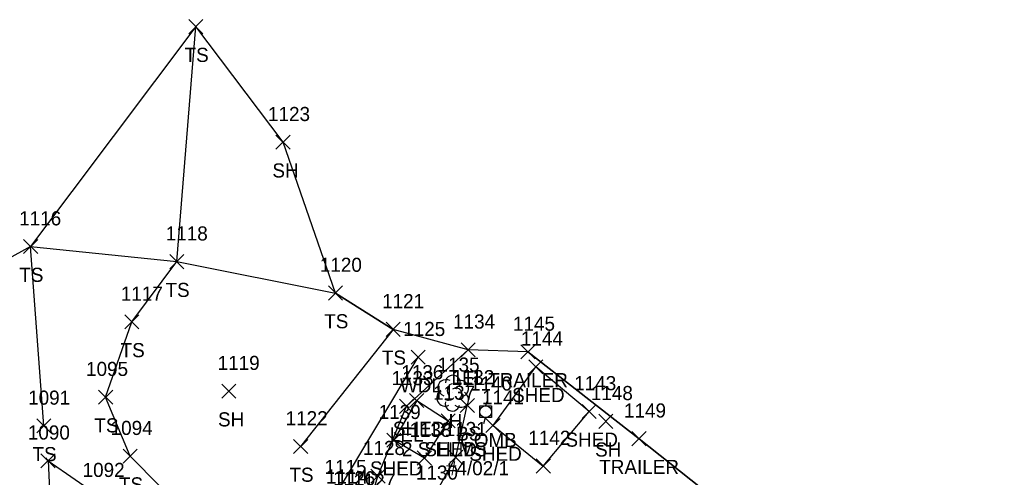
# Model space of a CAD drawing. Extents: x 1638344 to 1639591, y 610835 to 612202.
# Drawn here: x 1638740.9 to 1638879.7, y 611802.5 to 611867.3 of the extents above; entities that cross this region are included whole.
import ezdxf

# ---------------------------------------------------------------- set-up
doc = ezdxf.new("R2010")
doc.units = 0
for name, color, linetype in [('L_A', 7, 'Continuous'), ('L_C', 7, 'Continuous'), ('L_I', 7, 'Continuous'), ('L_TIC', 7, 'Continuous'), ('LARO', 7, 'Continuous'), ('LAWA', 7, 'Continuous'), ('LBC', 7, 'Continuous'), ('LELB', 7, 'Continuous'), ('LSOGP', 7, 'Continuous'), ('LTD', 7, 'Continuous'), ('U_A', 7, 'Continuous'), ('U_C', 7, 'Continuous'), ('U_I', 7, 'Continuous'), ('UP', 7, 'Continuous')]:
    doc.layers.add(name, color=color, linetype=linetype)

msp = doc.modelspace()

# ---------------------------------------------------------------- linework, layer by layer
at = {"layer": 'L_TIC'}
for points in [[(1638764.83, 611865.31), (1638766.83, 611867.31)], [(1638766.83, 611865.31), (1638764.83, 611867.31)], [(1638777.18, 611848.94), (1638779.18, 611850.94)], [(1638779.18, 611848.94), (1638777.18, 611850.94)], [(1638741.44, 611834.16), (1638743.44, 611836.16)], [(1638743.44, 611834.16), (1638741.44, 611836.16)], [(1638762.13, 611832.02), (1638764.13, 611834.02)], [(1638764.13, 611832.02), (1638762.13, 611834.02)], [(1638762.13, 611832.02), (1638764.13, 611834.02)], [(1638764.13, 611832.02), (1638762.13, 611834.02)], [(1638784.6, 611827.58), (1638786.6, 611829.58)], [(1638786.6, 611827.58), (1638784.6, 611829.58)], [(1638755.77, 611823.49), (1638757.77, 611825.49)], [(1638757.77, 611823.49), (1638755.77, 611825.49)], [(1638792.76, 611822.43), (1638794.76, 611824.43)], [(1638794.76, 611822.43), (1638792.76, 611824.43)], [(1638796.32, 611818.49), (1638798.32, 611820.49)], [(1638798.32, 611818.49), (1638796.32, 611820.49)], [(1638803.38, 611819.54), (1638805.38, 611821.54)], [(1638805.38, 611819.54), (1638803.38, 611821.54)], [(1638811.85, 611819.24), (1638813.85, 611821.24)], [(1638813.85, 611819.24), (1638811.85, 611821.24)], [(1638812.98, 611817.13), (1638814.98, 611819.13)], [(1638814.98, 611817.13), (1638812.98, 611819.13)], [(1638812.98, 611817.13), (1638814.98, 611819.13)], [(1638814.98, 611817.13), (1638812.98, 611819.13)], [(1638752.06, 611812.83), (1638754.06, 611814.83)], [(1638754.06, 611812.83), (1638752.06, 611814.83)], [(1638769.49, 611813.68), (1638771.49, 611815.68)], [(1638771.49, 611813.68), (1638769.49, 611815.68)], [(1638794.66, 611811.53), (1638796.66, 611813.53)], [(1638796.66, 611811.53), (1638794.66, 611813.53)], [(1638796.1, 611812.36), (1638798.1, 611814.36)], [(1638798.1, 611812.36), (1638796.1, 611814.36)], [(1638796.1, 611812.36), (1638798.1, 611814.36)], [(1638798.1, 611812.36), (1638796.1, 611814.36)], [(1638803.26, 611811.66), (1638805.26, 611813.66)], [(1638805.26, 611811.66), (1638803.26, 611813.66)], [(1638820.52, 611810.81), (1638822.52, 611812.81)], [(1638822.52, 611810.81), (1638820.52, 611812.81)], [(1638743.3, 611808.76), (1638745.3, 611810.76)], [(1638745.3, 611808.76), (1638743.3, 611810.76)], [(1638800.55, 611809.46), (1638802.55, 611811.46)], [(1638802.55, 611809.46), (1638800.55, 611811.46)], [(1638806.91, 611808.81), (1638808.91, 611810.81)], [(1638808.91, 611808.81), (1638806.91, 611810.81)], [(1638806.91, 611808.81), (1638808.91, 611810.81)], [(1638808.91, 611808.81), (1638806.91, 611810.81)], [(1638822.87, 611809.41), (1638824.87, 611811.41)], [(1638824.87, 611809.41), (1638822.87, 611811.41)], [(1638779.67, 611805.84), (1638781.67, 611807.84)], [(1638781.67, 611805.84), (1638779.67, 611807.84)], [(1638792.86, 611806.73), (1638794.86, 611808.73)], [(1638794.86, 611806.73), (1638792.86, 611808.73)], [(1638792.86, 611806.73), (1638794.86, 611808.73)], [(1638794.86, 611806.73), (1638792.86, 611808.73)], [(1638827.58, 611806.94), (1638829.58, 611808.94)], [(1638829.58, 611806.94), (1638827.58, 611808.94)], [(1638755.54, 611804.47), (1638757.54, 611806.47)], [(1638757.54, 611804.47), (1638755.54, 611806.47)], [(1638743.91, 611803.82), (1638745.91, 611805.82)], [(1638745.91, 611803.82), (1638743.91, 611805.82)], [(1638743.91, 611803.82), (1638745.91, 611805.82)], [(1638745.91, 611803.82), (1638743.91, 611805.82)], [(1638797.19, 611804.2), (1638799.19, 611806.2)], [(1638799.19, 611804.2), (1638797.19, 611806.2)], [(1638801.62, 611804.31), (1638803.62, 611806.31)], [(1638803.62, 611804.31), (1638801.62, 611806.31)], [(1638814.02, 611803.07), (1638816.02, 611805.07)], [(1638816.02, 611803.07), (1638814.02, 611805.07)], [(1638790.62, 611801.63), (1638792.62, 611803.63)], [(1638792.62, 611801.63), (1638790.62, 611803.63)]]:
    msp.add_lwpolyline(points, dxfattribs=at)
at = {"layer": 'LARO'}
msp.add_lwpolyline([(1638790.24, 611797.98), (1638791.62, 611802.63), (1638795.66, 611812.53), (1638804.38, 611820.54)], dxfattribs=at)
at = {"layer": 'LAWA'}
for points in [[(1638744.91, 611804.82), (1638752.57, 611799.52), (1638765.1, 611796.81), (1638772.62, 611792.56), (1638785.61, 611799.94), (1638797.32, 611819.49)], [(1638744.91, 611804.82), (1638745.51, 611792.4)]]:
    msp.add_lwpolyline(points, dxfattribs=at)
at = {"layer": 'LBC'}
for points in [[(1638812.85, 611820.24), (1638828.58, 611807.94), (1638844.61, 611795.24), (1638848.09, 611792.32), (1638864.73, 611779.22), (1638873.51, 611789.89)], [(1638807.91, 611809.81), (1638815.02, 611804.07), (1638821.52, 611811.81), (1638813.98, 611818.13)], [(1638807.91, 611809.81), (1638813.98, 611818.13)], [(1638797.1, 611813.36), (1638801.55, 611810.46), (1638798.19, 611805.2), (1638793.86, 611807.73)], [(1638797.1, 611813.36), (1638793.86, 611807.73)]]:
    msp.add_lwpolyline(points, dxfattribs=at)
at = {"layer": 'LELB'}
for points in [[(1638744.3, 611809.76), (1638742.44, 611835.16), (1638763.13, 611833.02), (1638765.83, 611866.31)], [(1638765.1, 611796.81), (1638756.54, 611805.47), (1638753.06, 611813.83), (1638756.77, 611824.49), (1638763.13, 611833.02), (1638785.6, 611828.58), (1638793.76, 611823.43), (1638780.67, 611806.84)], [(1638790.24, 611797.98), (1638792.84, 611793.99), (1638799.21, 611799.14), (1638802.62, 611805.31), (1638804.26, 611812.66)]]:
    msp.add_lwpolyline(points, dxfattribs=at)
at = {"layer": 'LSOGP'}
msp.add_lwpolyline([(1638882.1, 611783.04), (1638873.51, 611789.89), (1638864.73, 611779.22), (1638848.09, 611792.32), (1638844.61, 611795.24), (1638828.58, 611807.94), (1638812.85, 611820.24), (1638804.38, 611820.54), (1638793.76, 611823.43), (1638785.6, 611828.58), (1638778.18, 611849.94), (1638765.83, 611866.31), (1638742.44, 611835.16), (1638718.34, 611821.86)], dxfattribs=at)
at = {"layer": 'LTD'}
msp.add_line((1638802.18, 611814.44), (1638802.18, 611814.44), dxfattribs=at)
msp.add_line((1638802.18, 611814.44), (1638802.18, 611814.44), dxfattribs=at)
msp.add_arc((1638802.22, 611815.88), 1.05, 335.5272, 180.9563, dxfattribs=at)
for centre, major_axis, ratio, start_param, end_param in [((1638801.38, 611815.11), (1.21, -0.51), 0.895232, 1.570796, 4.712389), ((1638803.22, 611815.03), (-1.14, -0.48), 0.949671, 1.570796, 4.712389), ((1638801.09, 611813.74), (0.58, -1.04), 0.959034, 3.141593, 6.283185), ((1638801.97, 611814.9), (-0.208, -0.792), 0.645439, 3.141593, 6.283185), ((1638802.68, 611814.28), (-0.5, 0.667), 0.989748, 3.141593, 6.283185), ((1638801.72, 611813.69), (-0.625, -0.083), 0.423636, 0, 3.141593), ((1638803.18, 611813.61), (-1.09, 0.79), 0.841452, 1.570796, 4.712389), ((1638802.18, 611812.94), (0.26, 1.06), 0.942809, 1.570796, 4.712389)]:
    msp.add_ellipse(centre, major_axis=major_axis, ratio=ratio, start_param=start_param, end_param=end_param, dxfattribs=at)
at = {"layer": 'UP'}
for p, q in [((1638807.11, 611813.43), (1638806.86, 611812.59)), ((1638806.03, 611810.93), (1638806.03, 611812.59)), ((1638806.03, 611812.59), (1638807.69, 611812.59)), ((1638807.69, 611812.59), (1638807.69, 611810.93)), ((1638807.69, 611810.93), (1638806.03, 611810.93)), ((1638806.61, 611810.09), (1638806.86, 611810.93)), ((1638806.86, 611811.76), (1638806.86, 611811.76))]:
    msp.add_line(p, q, dxfattribs=at)
msp.add_circle((1638806.86, 611811.76), 0.833, dxfattribs=at)

# ---------------------------------------------------------------- texts
at = {"layer": 'L_A'}
for s, p in [('TS', (1638764.24, 611861.31)), ('SH', (1638776.67, 611844.94)), ('TS', (1638740.84, 611830.16)), ('TS', (1638761.54, 611828.02)), ('TS', (1638761.54, 611828.02)), ('TS', (1638784.01, 611823.58)), ('TS', (1638755.18, 611819.49)), ('TS', (1638792.17, 611818.43)), ('LEL', (1638802.02, 611815.54)), ('WDL', (1638794.73, 611814.49)), ('TRAILER', (1638807.21, 611815.24)), ('SHED', (1638810.61, 611813.13)), ('SHED', (1638810.61, 611813.13)), ('TS', (1638751.47, 611808.83)), ('SH', (1638768.97, 611809.68)), ('H', (1638801.61, 611809.44)), ('LEL', (1638793.3, 611807.53)), ('SHED', (1638793.73, 611808.36)), ('SHED', (1638793.73, 611808.36)), ('BS', (1638802.7, 611807.66)), ('SHED', (1638818.16, 611806.81)), ('TS', (1638742.71, 611804.76)), ('SHED', (1638798.19, 611805.46)), ('SHED', (1638804.55, 611804.81)), ('SHED', (1638804.55, 611804.81)), ('SH', (1638822.36, 611805.41)), ('TRAILER', (1638822.94, 611802.94)), ('TS', (1638779.08, 611801.84)), ('SHED', (1638790.49, 611802.73)), ('SHED', (1638790.49, 611802.73)), ('TS', (1638754.95, 611800.47))]:
    msp.add_text(s, height=2, dxfattribs=at).set_placement(p)
at = {"layer": 'L_C'}
msp.add_text('2 S ELMS', height=2, dxfattribs=at).set_placement((1638795.01, 611805.44))
at = {"layer": 'L_I'}
for s, p in [('1123', (1638776.05, 611852.94)), ('1116', (1638740.82, 611838.16)), ('1118', (1638761.57, 611836.02)), ('1118', (1638761.57, 611836.02)), ('1120', (1638783.39, 611831.58)), ('1117', (1638755.21, 611827.49)), ('1121', (1638792.2, 611826.43)), ('1125', (1638795.19, 611822.49)), ('1134', (1638802.25, 611823.54)), ('1145', (1638810.73, 611823.24)), ('1144', (1638811.85, 611821.13)), ('1144', (1638811.85, 611821.13)), ('1095', (1638750.29, 611816.83)), ('1119', (1638768.92, 611817.68)), ('1135', (1638800.05, 611817.44)), ('1133', (1638793.54, 611815.53)), ('1136', (1638794.92, 611816.36)), ('1136', (1638794.92, 611816.36)), ('1132', (1638802.13, 611815.66)), ('1143', (1638819.4, 611814.81)), ('1091', (1638742.09, 611812.76)), ('1137', (1638799.42, 611813.46)), ('1141', (1638806.35, 611812.81)), ('1141', (1638806.35, 611812.81)), ('1148', (1638821.75, 611813.41)), ('1139', (1638791.72, 611810.73)), ('1139', (1638791.72, 611810.73)), ('1149', (1638826.45, 611810.94)), ('1094', (1638753.77, 611808.47)), ('1122', (1638778.54, 611809.84)), ('1090', (1638742.05, 611807.82)), ('1090', (1638742.05, 611807.82)), ('1138', (1638796.07, 611808.2)), ('1131', (1638801.06, 611808.31)), ('1142', (1638812.9, 611807.07)), ('1128', (1638789.49, 611805.63)), ('1115', (1638784.05, 611802.94)), ('1092', (1638749.8, 611802.52)), ('1114', (1638784.25, 611801.58)), ('1130', (1638796.99, 611802.14)), ('1126', (1638785.28, 611801.33)), ('1127', (1638788.11, 611800.98)), ('1127', (1638788.11, 611800.98))]:
    msp.add_text(s, height=2, dxfattribs=at).set_placement(p)
at = {"layer": 'U_A'}
msp.add_text('COMB', height=2, dxfattribs=at).set_placement((1638803.25, 611806.76))
at = {"layer": 'U_C'}
msp.add_text('#4/02/1', height=2, dxfattribs=at).set_placement((1638801.24, 611802.76))
at = {"layer": 'U_I'}
msp.add_text('1140', height=2, dxfattribs=at).set_placement((1638804.65, 611814.76))

doc.saveas('drawing.dxf')
